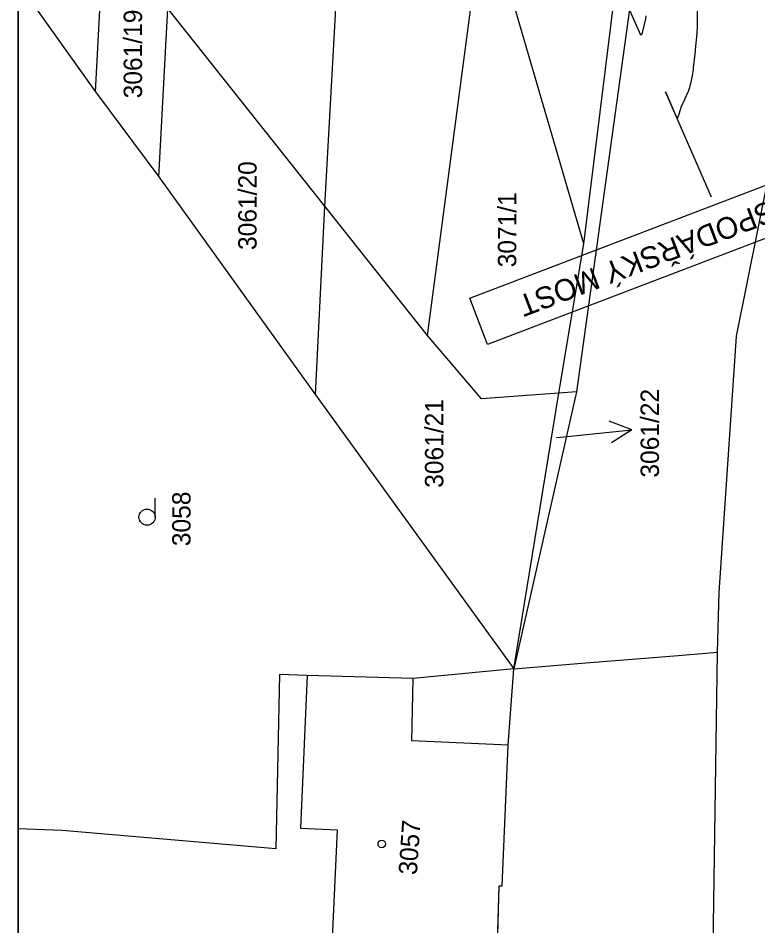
# Model space of a CAD drawing. Extents: x -534410 to -534262, y -1190162 to -1189584.
# Drawn here: x -534410.13 to -534375.88, y -1189988.37 to -1189946.36 of the extents above; entities that cross this region are included whole.
import ezdxf

# ---------------------------------------------------------------- set-up
doc = ezdxf.new("R2010")
doc.units = 0
for name, color, linetype in [('30', 7, 'Continuous'), ('31', 7, 'Continuous'), ('_N_text', 7, 'Continuous'), ('_rámeček', 7, 'Continuous'), ('_rámeček_mřížka', 7, 'Continuous'), ('Hranice parcel', 7, 'Continuous'), ('Parcelní čísla', 7, 'Continuous'), ('Polygon budovy', 7, 'Continuous'), ('Pop  PČ popisy', 7, 'Continuous'), ('Značky budov', 7, 'Continuous'), ('Značky kultur', 7, 'Continuous')]:
    doc.layers.add(name, color=color, linetype=linetype)

msp = doc.modelspace()

# ---------------------------------------------------------------- linework, layer by layer
at = {"layer": '30'}
msp.add_lwpolyline([(-534383.296, -1189942.636), (-534381.381, -1189946.992), (-534381.325, -1189947.092), (-534381.276, -1189947.123), (-534381.234, -1189947.083), (-534381.198, -1189946.974), (-534381.07, -1189946.397), (-534381.043, -1189946.252)], dxfattribs=at)
at = {"layer": '31'}
msp.add_lwpolyline([(-534378.02, -1189954.638), (-534380.16, -1189949.769), (-534380.099, -1189949.909), (-534379.628, -1189950.98), (-534379.618, -1189950.997), (-534379.609, -1189951.002), (-534379.6, -1189950.996), (-534379.592, -1189950.979), (-534379.557, -1189950.889), (-534379.549, -1189950.867), (-534379.541, -1189950.844), (-534379.533, -1189950.821), (-534379.526, -1189950.799), (-534379.474, -1189950.626), (-534379.463, -1189950.59), (-534379.45, -1189950.554), (-534379.436, -1189950.519), (-534379.422, -1189950.484), (-534379.095, -1189949.734), (-534379.061, -1189949.649), (-534379.031, -1189949.563), (-534379.006, -1189949.475), (-534378.985, -1189949.385), (-534378.91, -1189949.025), (-534378.893, -1189948.934), (-534378.878, -1189948.844), (-534378.865, -1189948.753), (-534378.854, -1189948.661), (-534378.772, -1189947.884), (-534378.771, -1189947.872), (-534378.769, -1189947.86), (-534378.765, -1189947.837), (-534378.763, -1189947.825), (-534378.761, -1189947.813), (-534378.695, -1189947.074), (-534378.686, -1189946.959), (-534378.679, -1189946.844), (-534378.674, -1189946.729), (-534378.672, -1189946.614), (-534378.666, -1189945.96)], dxfattribs=at)
at = {"layer": '_N_text'}
msp.add_lwpolyline([(-534358.995, -1189950.253), (-534388.393, -1189961.469), (-534389.213, -1189959.319), (-534359.815, -1189948.103)], close=True, dxfattribs=at)
at = {"layer": '_rámeček'}
msp.add_line((-534410.126, -1189584.47), (-534410.126, -1190161.97), dxfattribs=at)
msp.add_lwpolyline([(-534410.126, -1189899.47), (-534261.626, -1189899.47), (-534261.626, -1190004.47), (-534410.126, -1190004.47)], close=True, dxfattribs=at)
at = {"layer": '_rámeček_mřížka'}
msp.add_line((-534410.126, -1189584.47), (-534410.126, -1190161.97), dxfattribs=at)
at = {"layer": 'Hranice parcel'}
for p, q in [((-534391.18, -1189961.04), (-534385.61, -1189919.11)), ((-534406.54, -1189949.77), (-534406.13, -1189942)), ((-534410.126, -1189944.756), (-534406.54, -1189949.77)), ((-534403.61, -1189953.7), (-534403.19, -1189945.91)), ((-534395.93, -1189955.06), (-534403.19, -1189945.91)), ((-534406.54, -1189949.77), (-534403.61, -1189953.7)), ((-534403.61, -1189953.7), (-534396.36, -1189963.8)), ((-534396.36, -1189963.8), (-534395.93, -1189955.06)), ((-534391.18, -1189961.04), (-534395.93, -1189955.06)), ((-534385.09, -1189963.71), (-534383.94, -1189956.8)), ((-534396.36, -1189963.8), (-534387.17, -1189976.47)), ((-534384.28, -1189963.65), (-534387.17, -1189976.47)), ((-534387.17, -1189976.47), (-534385.09, -1189963.71)), ((-534384.28, -1189963.65), (-534385.09, -1189963.71)), ((-534388.01, -1189991.75), (-534387.85, -1189986.52))]:
    msp.add_line(p, q, dxfattribs=at)
for points in [[(-534395.93, -1189955.06), (-534393.76, -1189916.2), (-534389.49, -1189774.63), (-534390.92, -1189749.37)], [(-534383.94, -1189956.8), (-534379.19, -1189918.48), (-534376.74, -1189853.94), (-534375.92, -1189797.44), (-534376.41, -1189774.02), (-534378.12, -1189750.26)], [(-534373.61, -1189764.09), (-534375.04, -1189897.07), (-534384.28, -1189963.65)], [(-534383.94, -1189956.8), (-534387.37, -1189945.01), (-534385.61, -1189919.11)], [(-534377.74, -1189975.71), (-534377.67, -1189972.94), (-534376.87, -1189961.07), (-534375.31, -1189953.34)], [(-534385.09, -1189963.71), (-534388.68, -1189963.97), (-534391.18, -1189961.04)], [(-534387.17, -1189976.47), (-534383.85, -1189976.2), (-534379.76, -1189975.87), (-534377.74, -1189975.71)], [(-534380.79, -1190075.34), (-534378.76, -1190045.09), (-534377.74, -1189975.71)], [(-534387.17, -1189976.47), (-534391.84, -1189976.92), (-534396.75, -1189976.78), (-534398.02, -1189976.74), (-534398.19, -1189984.8), (-534408.09, -1189983.96), (-534410.126, -1189983.877)], [(-534387.85, -1189986.52), (-534387.71, -1189986.52), (-534387.44, -1189980.01), (-534387.17, -1189976.47)]]:
    msp.add_lwpolyline(points, dxfattribs=at)
at = {"layer": 'Polygon budovy'}
msp.add_lwpolyline([(-534397.05, -1189983.85), (-534395.35, -1189983.92), (-534395.59, -1189988.94), (-534400.44, -1189988.72), (-534400.58, -1189991.34), (-534398.09, -1189991.44), (-534388.01, -1189991.75), (-534387.85, -1189986.52), (-534387.71, -1189986.52), (-534387.44, -1189980.01), (-534391.9, -1189979.81), (-534391.84, -1189976.92), (-534396.75, -1189976.78)], close=True, dxfattribs=at)
at = {"layer": 'Pop  PČ popisy'}
for p, q in [((-534381.715, -1189965.406), (-534382.764, -1189965.013)), ((-534384.7, -1189965.72), (-534381.715, -1189965.406)), ((-534381.715, -1189965.406), (-534382.659, -1189966.009)), ((-534385.2, -1189965.77), (-534384.7, -1189965.72))]:
    msp.add_line(p, q, dxfattribs=at)
at = {"layer": 'Značky budov'}
msp.add_circle((-534393.29, -1189984.577), 0.175, dxfattribs=at)
at = {"layer": 'Značky kultur'}
msp.add_line((-534403.782, -1189969.455), (-534403.782, -1189968.58), dxfattribs=at)
msp.add_circle((-534404.157, -1189969.455), 0.375, dxfattribs=at)

# ---------------------------------------------------------------- texts
at = {"layer": '_N_text'}
msp.add_text('Ř. KM 0,6272 - 0,6377: HOSPODÁŘSKÝ MOST', height=1, rotation=200.9032, dxfattribs=at).set_placement((-534360.199, -1189948.996))
at = {"layer": 'Parcelní čísla'}
for s, rotation, p in [('3061/19', 90, (-534404.39, -1189950.071)), ('3061/20', 90, (-534399.086, -1189957.089)), ('3071/1', 90, (-534387.065, -1189957.891)), ('3061/22', 90, (-534380.458, -1189967.626)), ('3061/21', 90, (-534390.442, -1189968.097)), ('3058', 90, (-534402.143, -1189970.798)), ('3057', 86, (-534391.669, -1189986.029))]:
    msp.add_text(s, height=0.85, rotation=rotation, dxfattribs=at).set_placement(p)

doc.saveas('drawing.dxf')
